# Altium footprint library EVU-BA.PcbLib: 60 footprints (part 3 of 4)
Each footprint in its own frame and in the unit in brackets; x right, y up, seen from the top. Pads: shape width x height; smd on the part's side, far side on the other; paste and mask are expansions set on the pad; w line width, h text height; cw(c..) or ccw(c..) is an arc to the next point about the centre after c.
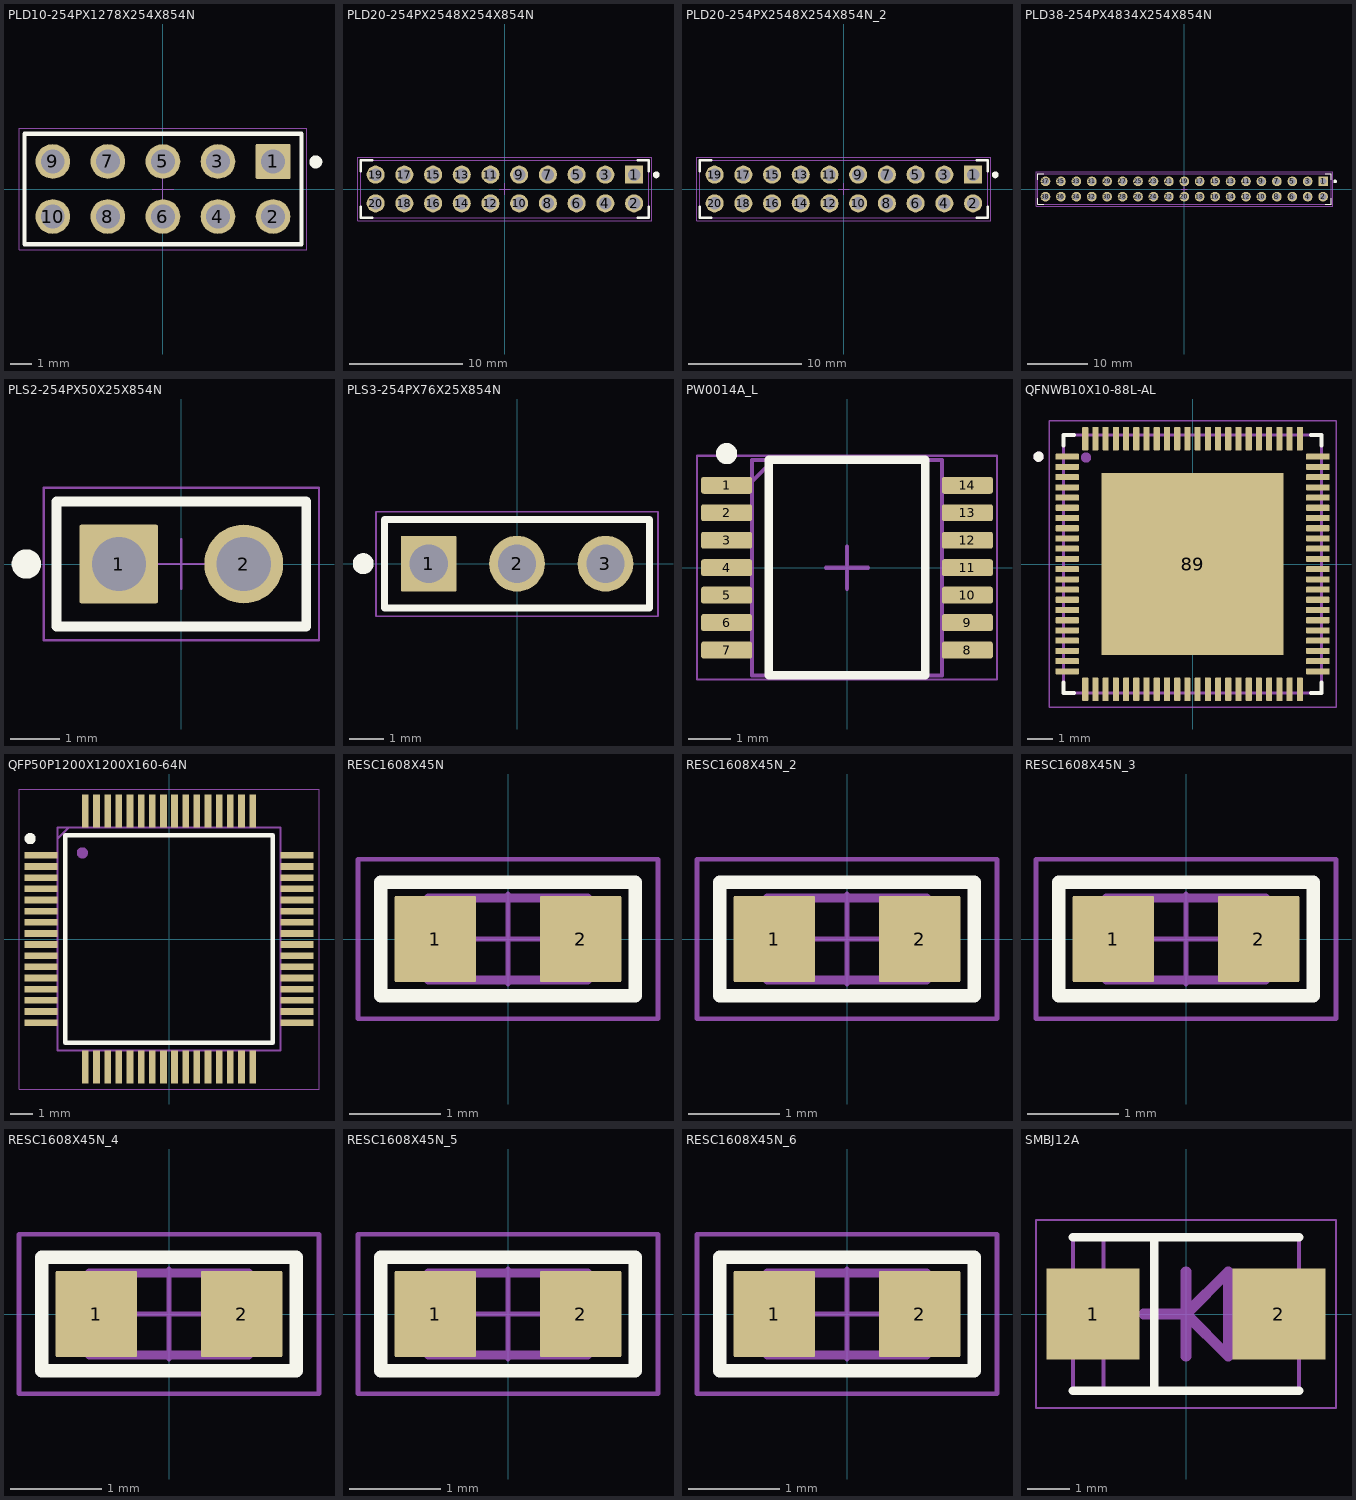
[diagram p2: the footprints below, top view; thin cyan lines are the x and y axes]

## PLD10-254PX1278X254X854N [mil]
pads (10):
  rrect5% 63x63 hole 43.31 mask+2.76: 1(200,50)
  round 63 hole 43.31 mask+2.76: 2(200,-50) 3(100,50) 4(100,-50) 5(0,50) 6(0,-50) 7(-100,50) 8(-100,-50) 9(-200,50) 10(-200,-50)
Top Overlay:
  circle w11.81: c277.56,49.21 r5.91
  lines w7.87: -251.57,-100.39 -251.57,100.39 251.57,100.39 251.57,-100.39 -251.57,-100.39
Top Assembly:
  circle w11.81: c200,49.21 r5.91
  lines w3.94: -251.57,-100.39 -251.57,100.39 251.57,100.39 251.57,-100.39 -251.57,-100.39
Top Designator:
  text ".Designator" at -127.95,-11.81 h59.06
Top Courtyard:
  lines w1.97: -19.68,0 19.68,0 ; 0,-19.68 0,19.68 ; -261.42,-110.24 -261.42,110.24 261.42,110.24 261.42,-110.24 -261.42,-110.24
3D body "BPDC-10.stp": height 337.35, standoff -116.98, extent -250,-101.18 250,98.82
3D body "PCB_Jumper.STEP": height 639.37, standoff 98.82, extent -250.2,7.87 -157.68,204.72
3D body "PCB_Jumper.STEP": height 639.37, standoff 98.82, extent -150.2,7.87 -57.68,204.72
3D body "PCB_Jumper.STEP": height 639.37, standoff 98.82, extent -50.2,7.87 42.32,204.72
3D body "PCB_Jumper.STEP": height 639.37, standoff 98.82, extent 49.8,7.87 142.32,204.72

## PLD20-254PX2548X254X854N [mil]
pads (20):
  rrect5% 63x63 hole 43.31 mask+2.76: 1(450,50)
  round 63 hole 43.31 mask+2.76: 2(450,-50) 3(350,50) 4(350,-50) 5(250,50) 6(250,-50) 7(150,50) 8(150,-50) 9(50,50) 10(50,-50) 11(-50,50) 12(-50,-50) 13(-150,50) 14(-150,-50) 15(-250,50) 16(-250,-50) 17(-350,50) 18(-350,-50) 19(-450,50) 20(-450,-50)
Top Overlay:
  circle w11.81: c527.56,49.21 r5.91
  lines w7.87: -501.57,-61.02 -501.57,-100.39 -462.2,-100.39 ; -501.57,61.02 -501.57,100.39 -462.2,100.39 ; 462.2,-100.39 501.57,-100.39 501.57,-61.02 ; 462.2,100.39 501.57,100.39 501.57,61.02
Bottom Overlay:
  circle w11.81: c501.57,100.39 r5.91
Top Assembly:
  circle w11.81: c451,50 r5.91
  lines w3.94: -501.57,-100.39 501.57,-100.39 501.57,100.39 -501.57,100.39 -501.57,-100.39
Top Designator:
  text ".Designator" at -127.95,-11.81 h59.06
Top Courtyard:
  lines w1.97: -19.68,0 19.68,0 ; 0,-19.68 0,19.68 ; -511.42,-110.24 511.42,-110.24 511.42,110.24 -511.42,110.24 -511.42,-110.24
3D body "TSW-110-09-L-D.stp": height 330, standoff -400, extent -500,-100 500,100

## PLD20-254PX2548X254X854N_2 [mil]
pads (20):
  rrect5% 63x63 hole 43.31 mask+2.76: 1(450,50)
  round 63 hole 43.31 mask+2.76: 2(450,-50) 3(350,50) 4(350,-50) 5(250,50) 6(250,-50) 7(150,50) 8(150,-50) 9(50,50) 10(50,-50) 11(-50,50) 12(-50,-50) 13(-150,50) 14(-150,-50) 15(-250,50) 16(-250,-50) 17(-350,50) 18(-350,-50) 19(-450,50) 20(-450,-50)
Top Overlay:
  circle w11.81: c527.56,49.21 r5.91
  lines w7.87: -501.57,-61.02 -501.57,-100.39 -462.2,-100.39 ; -501.57,61.02 -501.57,100.39 -462.2,100.39 ; 462.2,-100.39 501.57,-100.39 501.57,-61.02 ; 462.2,100.39 501.57,100.39 501.57,61.02
Bottom Overlay:
  circle w11.81: c501.57,100.39 r5.91
Top Assembly:
  circle w11.81: c451,50 r5.91
  lines w3.94: -501.57,-100.39 501.57,-100.39 501.57,100.39 -501.57,100.39 -501.57,-100.39
Top Designator:
  text ".Designator" at -127.95,-11.81 h59.06
Top Courtyard:
  lines w1.97: -19.68,0 19.68,0 ; 0,-19.68 0,19.68 ; -511.42,-110.24 511.42,-110.24 511.42,110.24 -511.42,110.24 -511.42,-110.24
3D body "TSW-110-09-L-D.stp": height 330, standoff -400, extent -500,-100 500,100

## PLD38-254PX4834X254X854N [mil]
pads (38):
  rrect5% 63x63 hole 43.31 mask+2.76: 1(900,50)
  round 63 hole 43.31 mask+2.76: 2(900,-50) 3(800,50) 4(800,-50) 5(700,50) 6(700,-50) 7(600,50) 8(600,-50) 9(500,50) 10(500,-50) 11(400,50) 12(400,-50) 13(300,50) 14(300,-50) 15(200,50) 16(200,-50) 17(100,50) 18(100,-50) 19(0,50) 20(0,-50) 21(-100,50) 22(-100,-50) 23(-200,50) 24(-200,-50) 25(-300,50) 26(-300,-50) 27(-400,50) 28(-400,-50) 29(-500,50) 30(-500,-50) 31(-600,50) 32(-600,-50) 33(-700,50) 34(-700,-50) 35(-800,50) 36(-800,-50) 37(-900,50) 38(-900,-50)
Top Overlay:
  circle w11.81: c977.56,49.21 r5.91
  lines w7.87: -951.57,-61.02 -951.57,-100.39 -912.2,-100.39 ; -951.57,61.02 -951.57,100.39 -912.2,100.39 ; 912.2,-100.39 951.57,-100.39 951.57,-61.02 ; 912.2,100.39 951.57,100.39 951.57,61.02
Bottom Overlay:
  circle w11.81: c951.57,100.39 r5.91
Top Assembly:
  circle w11.81: c900,50 r5.91
  lines w3.94: -951.57,-100.39 -951.57,100.39 951.57,100.39 951.57,-100.39 -951.57,-100.39
Top Designator:
  text ".Designator" at -137.8,-11.81 h59.06
Top Courtyard:
  lines w1.97: -19.68,0 19.68,0 ; 0,-19.68 0,19.68 ; -961.42,-110.24 961.42,-110.24 961.42,110.24 -961.42,110.24 -961.42,-110.24
3D body "TSW-119-09-L-D.stp": height 330, standoff -400, extent -950,-100 950,100

## PLS2-254PX50X25X854N [mil]
pads (2):
  rrect5% 63x63 hole 43.31 mask+2.76: 1(-50,0)
  round 63 hole 43.31 mask+2.76: 2(50,0)
Top Overlay:
  circle w11.81: c-124.02,0 r5.91
  lines w7.87: -100,-50 100,-50 100,50 -100,50 -100,-50
Top Assembly:
  lines w3.94: -100,-50 100,-50 100,50 -100,50 -100,-50
  text "1" at -126.57,-15.55 h59.06
Top Designator:
  text ".Designator" at 44.69,15.75 h59.06
Top Courtyard:
  lines w1.97: -19.68,0 19.68,0 ; 0,-19.68 0,19.68 ; -110.24,-61.02 110.24,-61.02 110.24,61.02 -110.24,61.02 -110.24,-61.02
3D body "BPSC-02.stp": height 337.33, standoff -117, extent -100,-50 100,50

## PLS3-254PX76X25X854N [mil]
pads (3):
  rrect5% 63x63 hole 43.31 mask+2.76: 1(-100,0)
  round 63 hole 43.31 mask+2.76: 2(0,0) 3(100,0)
Top Overlay:
  circle w11.81: c-174.02,0 r5.91
  lines w7.87: -150,-50 -150,50 150,50 150,-50 -150,-50
Top Assembly:
  circle w11.81: c-100,0 r5.91
  lines w3.94: -150,-50 -150,50 150,50 150,-50 -150,-50
Top Designator:
  text ".Designator" at -127.95,-11.81 h59.06
Top Courtyard:
  lines w1.97: -159.45,-59.45 -159.45,58.66 159.45,58.66 159.45,-59.45 -159.45,-59.45 ; -19.68,0 19.68,0 -19.68,0 ; 0,-19.68 0,19.68 0,-19.68
3D body "BPSC-03.stp": height 337.4, standoff -116.93, extent -150,-50 150,50

## PW0014A_L [mm] "SOP, 14-Leads, Body 5.1x4.5mm, Pitch 0.65mm, IPC High Density"
height 1.2
pads (14):
  rrect25% 1.2x0.4 smd: 1(-2.85,1.95) 2(-2.85,1.3) 3(-2.85,0.65) 4(-2.85,0) 5(-2.85,-0.65) 6(-2.85,-1.3) 7(-2.85,-1.95) 8(2.85,-1.95) 9(2.85,-1.3) 10(2.85,-0.65) 11(2.85,0) 12(2.85,0.65) 13(2.85,1.3) 14(2.85,1.95)
Top Overlay:
  circle w0.25: c-2.85,2.7 r0.125
  lines w0.2: -1.85,-2.55 1.85,-2.55 1.85,2.55 -1.85,2.55 -1.85,-2.55
Mechanical 1:
  text ".Designator" at -1.524,-0.508 h1.02
Top Assembly:
  lines w0.1: -2.25,1.301 -2.25,1.356 ; -2.25,1.962 -2.25,2.041 -1.741,2.55 ; -2.25,-2.55 2.25,-2.55 2.25,2.55 -2.25,2.55 -2.25,-2.55
Mechanical 13:
  lines w0.1: -2.25,-2.55 2.25,-2.55 2.25,2.55 -2.25,2.55 -2.25,-2.55
Top Courtyard:
  lines w0.05: -3.55,-2.65 3.55,-2.65 3.55,2.65 -3.55,2.65 -3.55,-2.65
  lines w0.1: -0.5,0 0.5,0 ; 0,-0.5 0,0.5
3D body "PW0014AakaMTC14.stp": height 1, standoff 0, extent -3.21,-2.5 3.21,2.5

## QFNWB10X10-88L-AL [mm]
pads (89):
  rrect25% 0.92x0.24 smd: 1(-4.905,4.2) 2(-4.905,3.8) 3(-4.905,3.4) 4(-4.905,3) 5(-4.905,2.6) 6(-4.905,2.2) 7(-4.905,1.8) 8(-4.905,1.4) 9(-4.905,1) 10(-4.905,0.6) 11(-4.905,0.2) 12(-4.905,-0.2) 13(-4.905,-0.6) 14(-4.905,-1) 15(-4.905,-1.4) 16(-4.905,-1.8) 17(-4.905,-2.2) 18(-4.905,-2.6) 19(-4.905,-3) 20(-4.905,-3.4) 21(-4.905,-3.8) 22(-4.905,-4.2) 45(4.905,-4.2) 46(4.905,-3.8) 47(4.905,-3.4) 48(4.905,-3) 49(4.905,-2.6) 50(4.905,-2.2) 51(4.905,-1.8) 52(4.905,-1.4) 53(4.905,-1) 54(4.905,-0.6) 55(4.905,-0.2) 56(4.905,0.2) 57(4.905,0.6) 58(4.905,1) 59(4.905,1.4) 60(4.905,1.8) 61(4.905,2.2) 62(4.905,2.6) 63(4.905,3) 64(4.905,3.4) 65(4.905,3.8) 66(4.905,4.2)
  rrect25% 0.24x0.92 smd: 23(-4.2,-4.905) 24(-3.8,-4.905) 25(-3.4,-4.905) 26(-3,-4.905) 27(-2.6,-4.905) 28(-2.2,-4.905) 29(-1.8,-4.905) 30(-1.4,-4.905) 31(-1,-4.905) 32(-0.6,-4.905) 33(-0.2,-4.905) 34(0.2,-4.905) 35(0.6,-4.905) 36(1,-4.905) 37(1.4,-4.905) 38(1.8,-4.905) 39(2.2,-4.905) 40(2.6,-4.905) 41(3,-4.905) 42(3.4,-4.905) 43(3.8,-4.905) 44(4.2,-4.905) 67(4.2,4.905) 68(3.8,4.905) 69(3.4,4.905) 70(3,4.905) 71(2.6,4.905) 72(2.2,4.905) 73(1.8,4.905) 74(1.4,4.905) 75(1,4.905) 76(0.6,4.905) 77(0.2,4.905) 78(-0.2,4.905) 79(-0.6,4.905) 80(-1,4.905) 81(-1.4,4.905) 82(-1.8,4.905) 83(-2.2,4.905) 84(-2.6,4.905) 85(-3,4.905) 86(-3.4,4.905) 87(-3.8,4.905) 88(-4.2,4.905)
  rect 7.112x7.112 smd paste-3: 89(0,0)
Top Overlay:
  circle w0.2: c-6.025,4.2 r0.1
  lines w0.15: -5.05,-4.64 -5.05,-5.05 -4.64,-5.05 ; -5.05,4.64 -5.05,5.05 -4.64,5.05 ; 4.64,-5.05 5.05,-5.05 5.05,-4.64 ; 4.64,5.05 5.05,5.05 5.05,4.64
Top Paste:
  region: -1.27,1.27 -1.27,-1.27 1.27,-1.27 1.27,1.27
  region: 1.53,1.27 1.53,-1.27 3.4,-1.27 3.4,1.27
  region: -3.4,1.27 -3.4,-1.27 -1.53,-1.27 -1.53,1.27
  region: -3.4,3.4 -3.4,1.53 -1.53,1.53 -1.53,3.4
  region: -1.27,3.4 -1.27,1.53 1.27,1.53 1.27,3.4
  region: 1.53,3.4 1.53,1.53 3.4,1.53 3.4,3.4
  region: 1.53,-1.53 1.53,-3.4 3.4,-3.4 3.4,-1.53
  region: -1.27,-1.53 -1.27,-3.4 1.27,-3.4 1.27,-1.53
  region: -3.4,-1.53 -3.4,-3.4 -1.53,-3.4 -1.53,-1.53
Top Assembly:
  circle w0.2: c-4.166,4.166 r0.1
  lines w0.1: -5.05,4.194 -5.05,4.2
  lines w0.127: -5.05,-5.05 5.05,-5.05 5.05,5.05 -5.05,5.05 -5.05,-5.05
Mechanical 13:
  circle w0.2: c-6.025,4.2 r0.1
  lines w0.127: -5.05,-5.05 5.05,-5.05 5.05,5.05 -5.05,5.05 -5.05,-5.05
Top Courtyard:
  lines w0.05: -5.615,-5.615 5.615,-5.615 5.615,5.615 -5.615,5.615 -5.615,-5.615
3D body "BE-U1000.STEP": height 0.85, standoff -0.03, extent -5.001,-5.001 5.001,5.001

## QFP50P1200X1200X160-64N [mm]
pads (64):
  rect 1.475x0.3 smd: 1(-5.738,3.75) 2(-5.738,3.25) 3(-5.738,2.75) 4(-5.738,2.25) 5(-5.738,1.75) 6(-5.738,1.25) 7(-5.738,0.75) 8(-5.738,0.25) 9(-5.738,-0.25) 10(-5.738,-0.75) 11(-5.738,-1.25) 12(-5.738,-1.75) 13(-5.738,-2.25) 14(-5.738,-2.75) 15(-5.738,-3.25) 16(-5.738,-3.75) 33(5.738,-3.75) 34(5.738,-3.25) 35(5.738,-2.75) 36(5.738,-2.25) 37(5.738,-1.75) 38(5.738,-1.25) 39(5.738,-0.75) 40(5.738,-0.25) 41(5.738,0.25) 42(5.738,0.75) 43(5.738,1.25) 44(5.738,1.75) 45(5.738,2.25) 46(5.738,2.75) 47(5.738,3.25) 48(5.738,3.75)
  rect 0.3x1.475 smd: 17(-3.75,-5.738) 18(-3.25,-5.738) 19(-2.75,-5.738) 20(-2.25,-5.738) 21(-1.75,-5.738) 22(-1.25,-5.738) 23(-0.75,-5.738) 24(-0.25,-5.738) 25(0.25,-5.738) 26(0.75,-5.738) 27(1.25,-5.738) 28(1.75,-5.738) 29(2.25,-5.738) 30(2.75,-5.738) 31(3.25,-5.738) 32(3.75,-5.738) 49(3.75,5.738) 50(3.25,5.738) 51(2.75,5.738) 52(2.25,5.738) 53(1.75,5.738) 54(1.25,5.738) 55(0.75,5.738) 56(0.25,5.738) 57(-0.25,5.738) 58(-0.75,5.738) 59(-1.25,5.738) 60(-1.75,5.738) 61(-2.25,5.738) 62(-2.75,5.738) 63(-3.25,5.738) 64(-3.75,5.738)
Top Overlay:
  circle w0.25: c-6.225,4.5 r0.125
  lines w0.2: -4.65,-4.65 -4.65,4.65 4.65,4.65 4.65,-4.65 -4.65,-4.65
Top Assembly:
  circle w0.25: c-3.886,3.861 r0.125
  lines w0.1: -5,-5 -5,5 5,5 5,-5 -5,-5
Mechanical 13:
  lines w0.1: -5,4.5 -4.5,5 ; -5,-5 -5,5 5,5 5,-5 -5,-5
Top Courtyard:
  lines w0.05: -6.725,-6.725 -6.725,6.725 6.725,6.725 6.725,-6.725 -6.725,-6.725
3D body "FT2232HL-REEL.stp": height 1.6, standoff 0, extent -6,-6 6,6

## RESC1608X45N [mm]
height 11.25
pads (2):
  rrect5% 0.9x0.95 smd mask+0.07: 1(-0.8,0) 2(0.8,0)
Top Overlay:
  lines w0.15: -1.4,-0.625 -1.4,0.625 1.4,0.625 1.4,-0.625 -1.4,-0.625
Top Assembly:
  lines w0.1: -0.875,-0.45 0.875,-0.45 0.875,0.45 -0.875,0.45 -0.875,-0.45
Top Designator:
  text ".Designator" at -3.25,-0.3 h1.5
Mechanical 9:
  text ".MARK" at -1.725,-0.341 h1.5
Top Courtyard:
  lines w0.05: -0.5,0 0.5,0 ; 0,-0.5 0,0.5 ; -1.65,-0.875 1.65,-0.875 1.65,0.875 -1.65,0.875 -1.65,-0.875
3D body "RESC1608X06N.step": height 0.55, standoff 0, extent -0.85,-0.45 0.85,0.45

## RESC1608X45N_2 [mm]
pads (2):
  rrect5% 0.9x0.95 smd mask+0.07: 1(-0.8,0) 2(0.8,0)
Top Overlay:
  lines w0.15: -1.4,-0.625 -1.4,0.625 1.4,0.625 1.4,-0.625 -1.4,-0.625
Top Assembly:
  lines w0.1: -0.875,-0.45 0.875,-0.45 0.875,0.45 -0.875,0.45 -0.875,-0.45
Top Designator:
  text ".Designator" at -3.25,-0.3 h1.5
Mechanical 9:
  text ".MARK" at -1.725,-0.341 h1.5
Top Courtyard:
  lines w0.05: -0.5,0 0.5,0 ; 0,-0.5 0,0.5 ; -1.65,-0.875 1.65,-0.875 1.65,0.875 -1.65,0.875 -1.65,-0.875
3D body "RESC1608X06N.step": height 0.55, standoff 0, extent -0.85,-0.45 0.85,0.45

## RESC1608X45N_3 [mm]
pads (2):
  rrect5% 0.9x0.95 smd mask+0.07: 1(-0.8,0) 2(0.8,0)
Top Overlay:
  lines w0.15: -1.4,-0.625 -1.4,0.625 1.4,0.625 1.4,-0.625 -1.4,-0.625
Top Assembly:
  lines w0.1: -0.875,-0.45 0.875,-0.45 0.875,0.45 -0.875,0.45 -0.875,-0.45
Top Designator:
  text ".Designator" at -3.25,-0.3 h1.5
Mechanical 9:
  text ".MARK" at -1.725,-0.341 h1.5
Top Courtyard:
  lines w0.05: -0.5,0 0.5,0 ; 0,-0.5 0,0.5 ; -1.65,-0.875 1.65,-0.875 1.65,0.875 -1.65,0.875 -1.65,-0.875
3D body "RESC1608X06N.step": height 0.55, standoff 0, extent -0.85,-0.45 0.85,0.45

## RESC1608X45N_4 [mm]
pads (2):
  rrect5% 0.9x0.95 smd mask+0.07: 1(-0.8,0) 2(0.8,0)
Top Overlay:
  lines w0.15: -1.4,-0.625 1.4,-0.625 1.4,0.625 -1.4,0.625 -1.4,-0.625
Top Assembly:
  lines w0.1: -0.875,-0.45 -0.875,0.45 0.875,0.45 0.875,-0.45 -0.875,-0.45
Top Designator:
  text ".Designator" at -3.25,-0.3 h1.5
Mechanical 9:
  text ".MARK" at -1.725,-0.341 h1.5
Top Courtyard:
  lines w0.05: -0.5,0 0.5,0 ; 0,-0.5 0,0.5 ; -1.65,-0.875 -1.65,0.875 1.65,0.875 1.65,-0.875 -1.65,-0.875
3D body "RESC1608X06N.step": height 0.55, standoff 0, extent -0.85,-0.45 0.85,0.45

## RESC1608X45N_5 [mm]
pads (2):
  rrect5% 0.9x0.95 smd mask+0.07: 1(-0.8,0) 2(0.8,0)
Top Overlay:
  lines w0.15: -1.4,-0.625 1.4,-0.625 1.4,0.625 -1.4,0.625 -1.4,-0.625
Top Assembly:
  lines w0.1: -0.875,-0.45 -0.875,0.45 0.875,0.45 0.875,-0.45 -0.875,-0.45
Top Designator:
  text ".Designator" at -3.25,-0.3 h1.5
Mechanical 9:
  text ".MARK" at -1.725,-0.341 h1.5
Top Courtyard:
  lines w0.05: -0.5,0 0.5,0 ; 0,-0.5 0,0.5 ; -1.65,-0.875 -1.65,0.875 1.65,0.875 1.65,-0.875 -1.65,-0.875
3D body "RESC1608X06N.step": height 0.55, standoff 0, extent -0.85,-0.45 0.85,0.45

## RESC1608X45N_6 [mm]
pads (2):
  rrect5% 0.9x0.95 smd mask+0.07: 1(-0.8,0) 2(0.8,0)
Top Overlay:
  lines w0.15: -1.4,-0.625 1.4,-0.625 1.4,0.625 -1.4,0.625 -1.4,-0.625
Top Assembly:
  lines w0.1: -0.875,-0.45 -0.875,0.45 0.875,0.45 0.875,-0.45 -0.875,-0.45
Top Designator:
  text ".Designator" at -3.25,-0.3 h1.5
Mechanical 9:
  text ".MARK" at -1.725,-0.341 h1.5
Top Courtyard:
  lines w0.05: -0.5,0 0.5,0 ; 0,-0.5 0,0.5 ; -1.65,-0.875 -1.65,0.875 1.65,0.875 1.65,-0.875 -1.65,-0.875
3D body "RESC1608X06N.step": height 0.55, standoff 0, extent -0.85,-0.45 0.85,0.45

## SMBJ12A [mm]
pads (2):
  rect 2.2x2.15 smd: 1(-2.2,0) 2(2.2,0)
Top Overlay:
  lines w0.2: -2.675,-1.812 2.675,-1.812 ; -2.675,1.812 2.675,1.812 ; -0.75,-1.812 -0.75,1.812
Top Assembly:
  lines w0.1: -1.95,-1.8 -1.95,1.8 ; -2.675,-1.812 2.675,-1.812 2.675,1.812 -2.675,1.812 -2.675,-1.812
  lines w0.254: -1,0 0,0 ; 0,-1 0,1 ; 1,0 2,0 ; 0,0 1,1 1,-1 0,0
Mechanical 13:
  lines w0.1: -2.675,-1.812 2.675,-1.812 2.675,1.812 -2.675,1.812 -2.675,-1.812
Top Courtyard:
  lines w0.05: -3.55,-2.225 3.55,-2.225 3.55,2.225 -3.55,2.225 -3.55,-2.225
3D body "SMBJ48A-TR.stp": height 2.33, standoff 0.01, extent -2.675,-1.86 2.675,1.86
